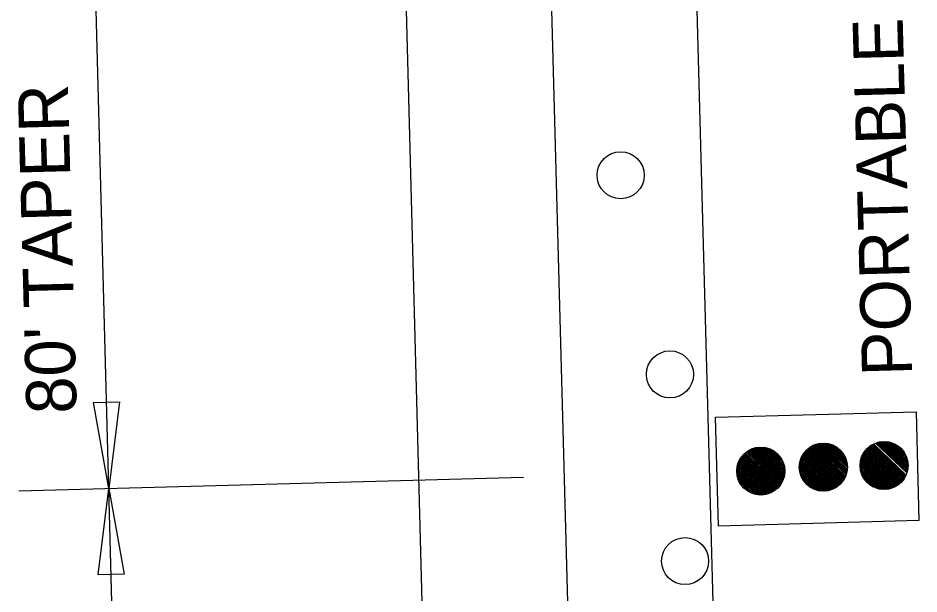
# Model space of a CAD drawing. Extents: x 1929624 to 1932607, y 596315 to 605533.
# Drawn here: x 1929771.7 to 1929881.9, y 598882.7 to 598953.1 of the extents above; entities that cross this region are included whole.
import ezdxf

# ---------------------------------------------------------------- set-up
doc = ezdxf.new("R2010")
doc.units = 0
doc.layers.add('Default', color=7, linetype='Continuous')

msp = doc.modelspace()

# ---------------------------------------------------------------- linework, layer by layer
at = {"layer": 'Default'}
for p, q in [((1929821.7, 598859.91), (1929806.81, 599414.78)), ((1929839.48, 598860.38), (1929824.59, 599415.26)), ((1929857.27, 598860.86), (1929842.37, 599415.74)), ((1929782.79, 598895.63), (1929780.8, 598969.54)), ((1929780.92, 598906.13), (1929784.09, 598906.21)), ((1929782.79, 598895.63), (1929780.92, 598906.13)), ((1929784.09, 598906.21), (1929782.79, 598895.63)), ((1929873.09, 598897.84), (1929869.64, 598901.12)), ((1929873.11, 598898), (1929869.8, 598901.14)), ((1929873.12, 598898.17), (1929869.96, 598901.16)), ((1929873.12, 598898.35), (1929870.14, 598901.17)), ((1929873.1, 598898.54), (1929870.33, 598901.16)), ((1929873.07, 598898.74), (1929870.54, 598901.14)), ((1929873.02, 598898.96), (1929870.76, 598901.11)), ((1929880.41, 598897.52), (1929876.56, 598901.17)), ((1929880.45, 598897.66), (1929876.7, 598901.22)), ((1929880.49, 598897.81), (1929876.84, 598901.26)), ((1929880.52, 598897.95), (1929876.99, 598901.3)), ((1929880.54, 598898.11), (1929877.14, 598901.33)), ((1929880.55, 598898.27), (1929877.31, 598901.35)), ((1929880.56, 598898.45), (1929877.48, 598901.36)), ((1929880.55, 598898.63), (1929877.66, 598901.37)), ((1929880.53, 598898.83), (1929877.86, 598901.36)), ((1929880.49, 598899.04), (1929878.07, 598901.33)), ((1929880.43, 598899.27), (1929878.31, 598901.28)), ((1929880.34, 598899.53), (1929878.58, 598901.21)), ((1929864.95, 598896.08), (1929860.73, 598900.08)), ((1929865.02, 598896.18), (1929860.83, 598900.15)), ((1929865.09, 598896.3), (1929860.94, 598900.23)), ((1929865.15, 598896.41), (1929861.05, 598900.3)), ((1929865.21, 598896.53), (1929861.17, 598900.36)), ((1929865.26, 598896.66), (1929861.29, 598900.42)), ((1929865.31, 598896.79), (1929861.42, 598900.48)), ((1929865.35, 598896.93), (1929861.55, 598900.53)), ((1929865.39, 598897.07), (1929861.69, 598900.57)), ((1929865.42, 598897.21), (1929861.84, 598900.61)), ((1929865.44, 598897.37), (1929861.99, 598900.64)), ((1929865.46, 598897.53), (1929862.15, 598900.67)), ((1929865.47, 598897.7), (1929862.32, 598900.68)), ((1929865.47, 598897.87), (1929862.49, 598900.69)), ((1929865.45, 598898.06), (1929862.68, 598900.69)), ((1929865.42, 598898.27), (1929862.89, 598900.67)), ((1929865.38, 598898.49), (1929863.11, 598900.63)), ((1929865.3, 598898.74), (1929863.37, 598900.57)), ((1929865.18, 598899.03), (1929863.66, 598900.46)), ((1929864.95, 598899.42), (1929864.07, 598900.26)), ((1929872.08, 598895.98), (1929867.84, 598900.01)), ((1929872.18, 598896.07), (1929867.92, 598900.11)), ((1929872.27, 598896.16), (1929868, 598900.2)), ((1929872.36, 598896.25), (1929868.09, 598900.3)), ((1929872.44, 598896.35), (1929868.18, 598900.38)), ((1929872.52, 598896.45), (1929868.28, 598900.47)), ((1929872.6, 598896.55), (1929868.38, 598900.55)), ((1929872.67, 598896.66), (1929868.48, 598900.63)), ((1929872.73, 598896.77), (1929868.59, 598900.7)), ((1929872.8, 598896.89), (1929868.7, 598900.77)), ((1929872.86, 598897.01), (1929868.82, 598900.83)), ((1929872.91, 598897.13), (1929868.94, 598900.9)), ((1929872.96, 598897.27), (1929869.07, 598900.95)), ((1929873, 598897.4), (1929869.2, 598901)), ((1929873.04, 598897.54), (1929869.34, 598901.05)), ((1929873.07, 598897.69), (1929869.49, 598901.08)), ((1929872.95, 598899.21), (1929871.01, 598901.05)), ((1929872.83, 598899.5), (1929871.31, 598900.94)), ((1929872.6, 598899.9), (1929871.72, 598900.73)), ((1929879.36, 598896.06), (1929875.16, 598900.04)), ((1929879.46, 598896.14), (1929875.23, 598900.15)), ((1929879.56, 598896.22), (1929875.31, 598900.25)), ((1929879.65, 598896.31), (1929875.39, 598900.35)), ((1929879.74, 598896.4), (1929875.47, 598900.44)), ((1929879.83, 598896.49), (1929875.56, 598900.53)), ((1929879.91, 598896.59), (1929875.66, 598900.62)), ((1929879.99, 598896.69), (1929875.76, 598900.71)), ((1929880.06, 598896.8), (1929875.86, 598900.78)), ((1929880.13, 598896.91), (1929875.96, 598900.86)), ((1929880.2, 598897.02), (1929876.07, 598900.93)), ((1929880.26, 598897.14), (1929876.19, 598901)), ((1929880.32, 598897.26), (1929876.31, 598901.06)), ((1929880.18, 598899.86), (1929878.91, 598901.07)), ((1929879.78, 598900.42), (1929879.49, 598900.69)), ((1929863.89, 598895.14), (1929859.85, 598898.97)), ((1929864, 598895.21), (1929859.91, 598899.09)), ((1929864.12, 598895.28), (1929859.97, 598899.21)), ((1929864.23, 598895.35), (1929860.04, 598899.32)), ((1929864.33, 598895.43), (1929860.11, 598899.43)), ((1929864.43, 598895.51), (1929860.19, 598899.53)), ((1929864.53, 598895.59), (1929860.27, 598899.63)), ((1929864.62, 598895.68), (1929860.35, 598899.73)), ((1929864.71, 598895.77), (1929860.44, 598899.82)), ((1929864.79, 598895.87), (1929860.53, 598899.91)), ((1929864.87, 598895.97), (1929860.63, 598899.99)), ((1929871.02, 598895.41), (1929867.32, 598898.91)), ((1929871.15, 598895.45), (1929867.35, 598899.05)), ((1929871.29, 598895.5), (1929867.4, 598899.19)), ((1929871.41, 598895.56), (1929867.45, 598899.32)), ((1929871.54, 598895.62), (1929867.5, 598899.44)), ((1929871.65, 598895.68), (1929867.56, 598899.56)), ((1929871.77, 598895.75), (1929867.62, 598899.68)), ((1929871.88, 598895.82), (1929867.69, 598899.79)), ((1929871.98, 598895.9), (1929867.76, 598899.9)), ((1929878.37, 598895.58), (1929874.73, 598899.03)), ((1929878.51, 598895.62), (1929874.77, 598899.17)), ((1929878.65, 598895.67), (1929874.81, 598899.31)), ((1929878.78, 598895.72), (1929874.85, 598899.44)), ((1929878.91, 598895.78), (1929874.91, 598899.57)), ((1929879.03, 598895.84), (1929874.96, 598899.7)), ((1929879.14, 598895.91), (1929875.02, 598899.82)), ((1929879.25, 598895.98), (1929875.09, 598899.93)), ((1929862.74, 598894.82), (1929859.59, 598897.81)), ((1929862.91, 598894.83), (1929859.6, 598897.98)), ((1929863.07, 598894.86), (1929859.61, 598898.14)), ((1929863.22, 598894.89), (1929859.64, 598898.29)), ((1929863.37, 598894.93), (1929859.67, 598898.44)), ((1929863.5, 598894.98), (1929859.7, 598898.58)), ((1929863.64, 598895.03), (1929859.75, 598898.71)), ((1929863.76, 598895.08), (1929859.8, 598898.84)), ((1929870.56, 598895.31), (1929867.24, 598898.45)), ((1929870.39, 598895.29), (1929867.24, 598898.28)), ((1929870.21, 598895.28), (1929867.24, 598898.1)), ((1929870.02, 598895.29), (1929867.25, 598897.91)), ((1929870.72, 598895.33), (1929867.26, 598898.61)), ((1929870.87, 598895.37), (1929867.29, 598898.76)), ((1929877.73, 598895.49), (1929874.67, 598898.38)), ((1929877.9, 598895.5), (1929874.68, 598898.56)), ((1929877.55, 598895.48), (1929874.68, 598898.2)), ((1929878.07, 598895.52), (1929874.69, 598898.72)), ((1929877.35, 598895.5), (1929874.7, 598898)), ((1929878.22, 598895.55), (1929874.71, 598898.88)), ((1929771.76, 598895.33), (1929833.49, 598896.99)), ((1929862.56, 598894.81), (1929859.59, 598897.63)), ((1929862.37, 598894.81), (1929859.6, 598897.44)), ((1929862.17, 598894.83), (1929859.63, 598897.24)), ((1929861.95, 598894.87), (1929859.68, 598897.01)), ((1929861.69, 598894.93), (1929859.76, 598896.77)), ((1929869.82, 598895.31), (1929867.28, 598897.71)), ((1929869.59, 598895.34), (1929867.33, 598897.49)), ((1929869.34, 598895.4), (1929867.41, 598897.24)), ((1929869.05, 598895.51), (1929867.53, 598896.95)), ((1929877.13, 598895.52), (1929874.74, 598897.79)), ((1929876.9, 598895.57), (1929874.8, 598897.55)), ((1929876.62, 598895.66), (1929874.9, 598897.29)), ((1929876.28, 598895.8), (1929875.07, 598896.95)), ((1929781.49, 598885.05), (1929782.79, 598895.63)), ((1929784.13, 598845.47), (1929782.79, 598895.63)), ((1929782.79, 598895.63), (1929784.65, 598885.13)), ((1929861.4, 598895.04), (1929859.88, 598896.47)), ((1929860.99, 598895.24), (1929860.1, 598896.08)), ((1929868.64, 598895.72), (1929867.75, 598896.56)), ((1929784.65, 598885.13), (1929781.49, 598885.05))]:
    msp.add_line(p, q, dxfattribs=at)
msp.add_lwpolyline([(1929857.35, 598891.03), (1929857, 598904.32), (1929881.52, 598904.98), (1929881.88, 598891.69)], close=True, dxfattribs=at)
for centre, radius in [((1929845.39, 598933.92), 2.88), ((1929851.42, 598909.57), 2.88), ((1929870.18, 598898.23), 2.94), ((1929877.61, 598898.43), 2.94), ((1929862.53, 598897.75), 2.94), ((1929853.27, 598886.74), 2.88)]:
    msp.add_circle(centre, radius, dxfattribs=at)

# ---------------------------------------------------------------- texts
for s, height, p in [('PORTABLE TRAFFIC SIGNAL SYSTEM', 6.1396, (1929881.06, 598909.44)), ("80' TAPER", 6.14, (1929778.85, 598904.81))]:
    msp.add_text(s, height=height, rotation=91.5377, dxfattribs=at).set_placement(p)

doc.saveas('drawing.dxf')
